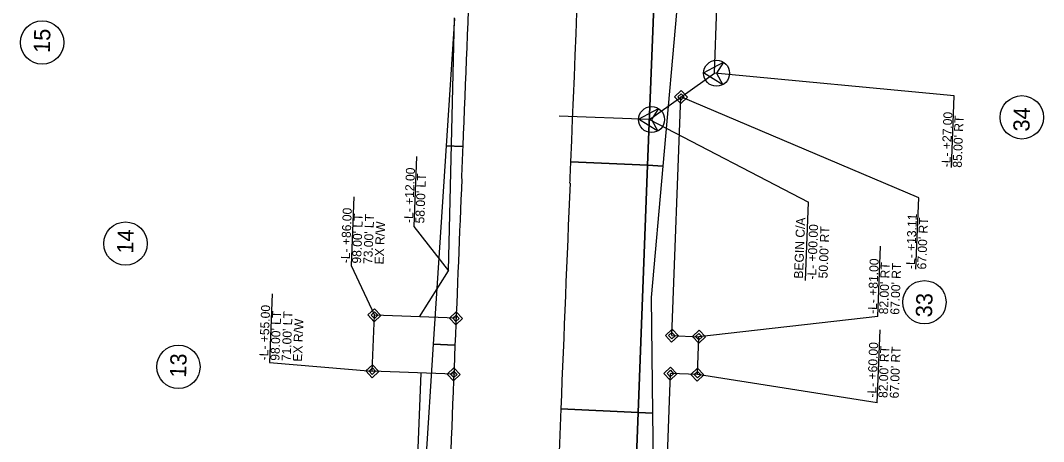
# Model space of a CAD drawing. Extents: x 2097272 to 2098144, y 685104 to 689282.
# Drawn here: x 2097467 to 2098034, y 687838 to 688071 of the extents above; entities that cross this region are included whole.
import ezdxf

# ---------------------------------------------------------------- set-up
doc = ezdxf.new("R2010")
doc.units = 0
for name, color, linetype in [('Prop Easement Construction', 7, 'Continuous'), ('Prop Easement Construction Station Offsets', 7, 'Continuous'), ('Prop Easement Permanent Utility', 7, 'Continuous'), ('Prop Easement Permanent Utility Station Offsets', 7, 'Continuous'), ('Prop Parcel Number CELL', 7, 'Continuous'), ('Prop ROW CA Lines', 7, 'Continuous'), ('Prop ROW Marker CELL', 7, 'Continuous'), ('Prop ROW Permanent Easement CELL', 7, 'Continuous'), ('Prop ROW RW Lines', 7, 'Continuous'), ('Prop ROW Station Offsets', 7, 'Continuous'), ('Scratch_Level_3', 7, 'Continuous'), ('Scratch_Level_6', 7, 'Continuous')]:
    doc.layers.add(name, color=color, linetype=linetype)

msp = doc.modelspace()

# ---------------------------------------------------------------- linework, layer by layer
at = {"layer": 'Prop Easement Construction'}
for p, q in [((2097704.34, 687932.25), (2097707.71, 688072.22)), ((2097688.36, 687906.84), (2097704.34, 687932.25)), ((2097685.03, 687767.87), (2097689.17, 687875.79))]:
    msp.add_line(p, q, dxfattribs=at)
at = {"layer": 'Prop Easement Construction Station Offsets'}
for p, q in [((2097686.73, 687995.61), (2097685.24, 687956.77)), ((2097685.24, 687956.77), (2097704.34, 687932.25))]:
    msp.add_line(p, q, dxfattribs=at)
at = {"layer": 'Prop Easement Permanent Utility'}
for p, q in [((2097828.06, 687896.48), (2097833.13, 688028.5)), ((2097662.19, 687876.82), (2097663.38, 687907.8)), ((2097708.57, 687906.07), (2097663.38, 687907.8)), ((2097828.06, 687896.48), (2097843.05, 687895.91)), ((2097842.25, 687874.92), (2097843.05, 687895.91)), ((2097707.32, 687875.09), (2097662.19, 687876.82)), ((2097708.15, 687875.06), (2097707.16, 687875.1)), ((2097708.15, 687875.06), (2097707.16, 687875.1)), ((2097819.44, 687658.64), (2097827.26, 687875.5)), ((2097842.25, 687874.92), (2097827.26, 687875.5))]:
    msp.add_line(p, q, dxfattribs=at)
at = {"layer": 'Prop Easement Permanent Utility Station Offsets'}
for p, q in [((2097964.77, 687972.77), (2097833.13, 688028.5)), ((2097651.98, 687973.34), (2097650.52, 687935.37)), ((2097963.26, 687933.23), (2097964.77, 687972.77)), ((2097942.2, 687907), (2097943.69, 687946.01)), ((2097650.52, 687935.37), (2097663.38, 687907.8)), ((2097606.76, 687919.56), (2097605.3, 687881.66)), ((2097942.2, 687907), (2097843.05, 687895.91)), ((2097941.82, 687859.39), (2097943.37, 687899.69)), ((2097605.3, 687881.66), (2097662.19, 687876.82)), ((2097941.82, 687859.39), (2097842.25, 687874.92))]:
    msp.add_line(p, q, dxfattribs=at)
at = {"layer": 'Prop Parcel Number CELL'}
for centre in [(2097479.34, 688058.64), (2098021.91, 688017.25), (2097525.5, 687947.38), (2097967.92, 687914.94), (2097554.79, 687879.22)]:
    msp.add_circle(centre, 12, dxfattribs=at)
at = {"layer": 'Prop ROW CA Lines'}
for p, q in [((2097851.65, 688041.68), (2097853.05, 688078.25)), ((2097815.64, 688016.04), (2097851.65, 688041.68)), ((2097815.64, 688016.04), (2097765.67, 688017.96))]:
    msp.add_line(p, q, dxfattribs=at)
at = {"layer": 'Prop ROW Marker CELL'}
for p, q in [((2097845.65, 688041.86), (2097856.62, 688047.79)), ((2097856.62, 688047.79), (2097852.84, 688041.65)), ((2097856.26, 688035.3), (2097845.65, 688041.86)), ((2097852.84, 688041.65), (2097856.26, 688035.3)), ((2097833.13, 688028.5), (2097833.13, 688028.5)), ((2097809.64, 688016.22), (2097820.62, 688022.15)), ((2097820.62, 688022.15), (2097816.84, 688016.01)), ((2097820.25, 688009.66), (2097809.64, 688016.22)), ((2097816.84, 688016.01), (2097820.25, 688009.66)), ((2097663.38, 687907.8), (2097663.38, 687907.8)), ((2097708.57, 687906.07), (2097708.57, 687906.07)), ((2097828.06, 687896.48), (2097828.06, 687896.48)), ((2097843.05, 687895.91), (2097843.05, 687895.91)), ((2097662.19, 687876.82), (2097662.19, 687876.82)), ((2097707.32, 687875.09), (2097707.32, 687875.09)), ((2097827.26, 687875.5), (2097827.26, 687875.5)), ((2097842.25, 687874.92), (2097842.25, 687874.92))]:
    msp.add_line(p, q, dxfattribs=at)
for centre in [(2097852.84, 688041.65), (2097816.84, 688016.01)]:
    msp.add_circle(centre, 7.2, dxfattribs=at)
at = {"layer": 'Prop ROW Permanent Easement CELL'}
for points in [[(2097829.53, 688028.6), (2097833.23, 688032.1), (2097836.72, 688028.39), (2097833.02, 688024.9)], [(2097831.33, 688028.55), (2097833.18, 688030.3), (2097834.93, 688028.45), (2097833.07, 688026.7)], [(2097659.78, 687907.91), (2097663.48, 687911.4), (2097666.97, 687907.7), (2097663.27, 687904.2)], [(2097661.58, 687907.85), (2097663.43, 687909.6), (2097665.18, 687907.75), (2097663.32, 687906)], [(2097704.97, 687906.17), (2097708.67, 687909.67), (2097712.16, 687905.96), (2097708.46, 687902.47)], [(2097706.77, 687906.12), (2097708.62, 687907.87), (2097710.37, 687906.02), (2097708.51, 687904.27)], [(2097824.47, 687896.59), (2097828.17, 687900.08), (2097831.66, 687896.38), (2097827.96, 687892.88)], [(2097826.26, 687896.53), (2097828.12, 687898.28), (2097829.86, 687896.43), (2097828.01, 687894.68)], [(2097839.45, 687896.01), (2097843.16, 687899.5), (2097846.65, 687895.8), (2097842.95, 687892.31)], [(2097841.25, 687895.96), (2097843.1, 687897.71), (2097844.85, 687895.85), (2097843, 687894.11)], [(2097658.59, 687876.93), (2097662.29, 687880.42), (2097665.79, 687876.72), (2097662.08, 687873.22)], [(2097660.39, 687876.88), (2097662.24, 687878.62), (2097663.99, 687876.77), (2097662.14, 687875.02)], [(2097703.72, 687875.2), (2097707.42, 687878.69), (2097710.91, 687874.99), (2097707.21, 687871.49)], [(2097823.66, 687875.6), (2097827.36, 687879.09), (2097830.86, 687875.39), (2097827.15, 687871.9)], [(2097825.46, 687875.55), (2097827.31, 687877.3), (2097829.06, 687875.44), (2097827.21, 687873.7)], [(2097838.65, 687875.03), (2097842.35, 687878.52), (2097845.85, 687874.82), (2097842.14, 687871.32)], [(2097705.52, 687875.14), (2097707.37, 687876.89), (2097709.12, 687875.04), (2097707.26, 687873.29)], [(2097840.45, 687874.97), (2097842.3, 687876.72), (2097844.05, 687874.87), (2097842.2, 687873.12)]]:
    msp.add_lwpolyline(points, close=True, dxfattribs=at)
at = {"layer": 'Prop ROW RW Lines'}
msp.add_line((2097775.94, 686980.56), (2097815.64, 688016.04), dxfattribs=at)
at = {"layer": 'Prop ROW Station Offsets'}
for p, q in [((2097984.47, 688029.07), (2097851.65, 688041.68)), ((2097982.95, 687989.53), (2097984.47, 688029.07)), ((2097815.64, 688016.04), (2097903.66, 687970.26)), ((2097902, 687926.98), (2097903.66, 687970.26))]:
    msp.add_line(p, q, dxfattribs=at)
at = {"layer": 'Scratch_Level_3'}
for p, q in [((2097814.67, 687990.72), (2097829.17, 688369.06)), ((2097772.16, 687992.7), (2097814.67, 687990.72)), ((2097814.67, 687990.72), (2097772.16, 687992.7)), ((2097809.42, 687853.94), (2097814.67, 687990.72)), ((2097766.6, 687855.99), (2097809.42, 687853.94)), ((2097809.42, 687853.94), (2097766.6, 687855.99)), ((2097803.54, 687700.51), (2097809.42, 687853.94))]:
    msp.add_line(p, q, dxfattribs=at)
for centre, radius, start, end in [((2013738.87, 691438.31), 84103.89, 357.6520239, 357.9090947), ((2013738.87, 691438.31), 84103.89, 357.643946, 357.6520239), ((2216468.39, 683097.18), 118797.14, 177.643946, 177.7042161), ((2216468.39, 683097.18), 118797.14, 177.7042161, 177.7780686)]:
    msp.add_arc(centre, radius, start, end, dxfattribs=at)
at = {"layer": 'Scratch_Level_6'}
for p, q in [((2097829.17, 688369.06), (2097814.67, 687990.72)), ((2097823.3, 687990.32), (2097834.52, 688117.08)), ((2097707.7, 688071.91), (2097703.11, 688001.47)), ((2097703.11, 688001.47), (2097695.97, 687891.79)), ((2097712.1, 688001.07), (2097703.11, 688001.47)), ((2097703.11, 688001.47), (2097712.1, 688001.07)), ((2097712.45, 688001.06), (2097712.1, 688001.07)), ((2097712.1, 688001.07), (2097712.45, 688001.06)), ((2097814.67, 687990.72), (2097809.42, 687853.94)), ((2097814.67, 687990.72), (2097823.3, 687990.32)), ((2097823.3, 687990.32), (2097814.67, 687990.72)), ((2097816.87, 687917.61), (2097823.3, 687990.32)), ((2097817.61, 687853.54), (2097816.87, 687917.61)), ((2097695.97, 687891.79), (2097683.51, 687700.25)), ((2097707.83, 687891.26), (2097695.97, 687891.79)), ((2097695.97, 687891.79), (2097707.83, 687891.26)), ((2097707.97, 687891.26), (2097707.83, 687891.26)), ((2097707.83, 687891.26), (2097707.97, 687891.26)), ((2097809.42, 687853.94), (2097803.54, 687700.51)), ((2097809.42, 687853.94), (2097817.61, 687853.54)), ((2097817.61, 687853.54), (2097809.42, 687853.94)), ((2097819.19, 687717.38), (2097817.61, 687853.54))]:
    msp.add_line(p, q, dxfattribs=at)
for centre, radius, start, end in [((2013738.87, 691438.31), 84043.89, 357.6560471, 357.7309688), ((2013738.87, 691438.31), 84043.89, 357.643946, 357.6560471), ((2216468.39, 683097.18), 118857.14, 177.643946, 177.6883627), ((2216468.39, 683097.18), 118857.14, 177.6883627, 177.7884999)]:
    msp.add_arc(centre, radius, start, end, dxfattribs=at)

# ---------------------------------------------------------------- texts
at = {"layer": 'Prop Easement Construction Station Offsets'}
for s, p in [('-L- +12.00', (2097684.69, 687958.72)), ("58.00' LT", (2097690.94, 687958.48))]:
    msp.add_text(s, height=5, rotation=87.8037, dxfattribs=at).set_placement(p)
at = {"layer": 'Prop Easement Permanent Utility Station Offsets'}
for s, p in [('-L- +86.00', (2097649.69, 687936.51)), ("98.00' LT", (2097655.93, 687936.27)), ("73.00' LT", (2097662.18, 687936.03)), ('-L- +13.11', (2097962.63, 687933.26)), ('EX R/W', (2097668.42, 687935.79)), ("67.00' RT", (2097968.88, 687933.02)), ('-L- +81.00', (2097941.5, 687908.44)), ("82.00' RT", (2097947.75, 687908.2)), ("67.00' RT", (2097953.99, 687907.96)), ('-L- +55.00', (2097604.47, 687882.74)), ("98.00' LT", (2097610.71, 687882.5)), ("71.00' LT", (2097616.96, 687882.26)), ('EX R/W', (2097623.21, 687882.02)), ('-L- +60.00', (2097941.18, 687862.15)), ("82.00' RT", (2097947.42, 687861.91)), ("67.00' RT", (2097953.67, 687861.67))]:
    msp.add_text(s, height=5, rotation=87.8037, dxfattribs=at).set_placement(p)
at = {"layer": 'Prop Parcel Number CELL'}
for s, p in [('15', (2097483.59, 688052.78)), ('34', (2098026.1, 688009.3)), ('14', (2097529.76, 687941.77)), ('33', (2097972.11, 687906.53)), ('13', (2097559.04, 687873.14))]:
    msp.add_text(s, height=9, rotation=88.3348, dxfattribs=at).set_placement(p)
at = {"layer": 'Prop ROW Station Offsets'}
for s, p in [('-L- +27.00', (2097982.33, 687989.55)), ("85.00' RT", (2097988.57, 687989.31)), ('BEGIN C/A', (2097900.68, 687927.94)), ('-L- +00.00', (2097907.93, 687927.4)), ("50.00' RT", (2097914.24, 687928.08))]:
    msp.add_text(s, height=5, rotation=87.8037, dxfattribs=at).set_placement(p)

doc.saveas('drawing.dxf')
